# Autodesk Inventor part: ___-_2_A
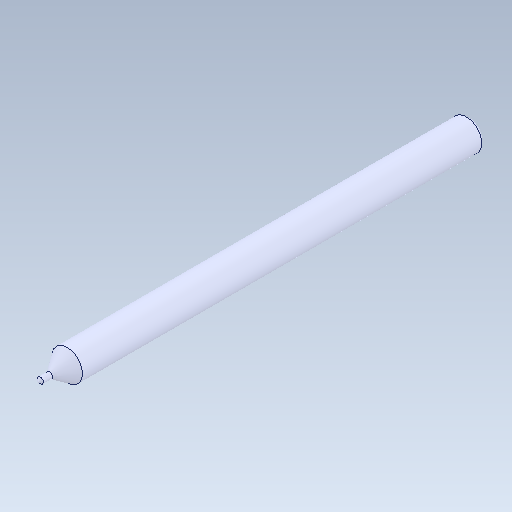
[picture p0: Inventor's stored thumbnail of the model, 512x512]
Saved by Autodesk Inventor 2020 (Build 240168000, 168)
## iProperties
Created: 2017-09
Part Number: ___-_2_A
Material: Générique
Document SubType Name: Modeling
Designer: bruno
Density: 1 g/cm^3
Appearance: Par défaut
Mass: 10.5216 g
Surface Area: 43.3998 cm^2
Volume: 10.5216 cm^3
Sending System: SolidWorks 2016
Author: bruno
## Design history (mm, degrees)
feature "Importée1"
node "Solide1"
